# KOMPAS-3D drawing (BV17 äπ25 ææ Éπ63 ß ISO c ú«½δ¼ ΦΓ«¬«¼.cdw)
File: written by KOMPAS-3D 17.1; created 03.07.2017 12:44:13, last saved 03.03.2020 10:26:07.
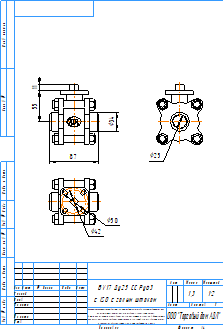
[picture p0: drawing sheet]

Sheet 1: A4, portrait

Title block, sheet 1: name: BV17 Ду25 СС Ру63 / с ISO c голым штоком; material: Сталь 20  ГОСТ 1050-88; mass: 1,3; sheets: 1; sheet format: A4; stored path: C:\Users\kka\KOMPAS_Work\!Trash\СС02 СС03 ФФ Смотровые стекла\СС01.cdw

Views: Спереди 4, Проекционный вид 5, Проекционный вид 6
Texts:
  Klimkovich
  ADL
  Рама для чертежей
  Лит-Масса-Масштаб
  Материал-Предприятие
  Масштаб
  Изм.
  Лист
  № докум.
  Подп.
  Дата
  Лит.
  Разраб.
  Пров.
  Т.контр.
  Листов
  Внимание! Данный продукт является объектом авторского права ООО «Торговый Дом АДЛ».
  Запрещается изменение, копирование, распространение
  (в том числе путем копирования на другие сайты и ресурсы в Интернете)
  или любое иное использование информации и объектов без предварительного
  согласия правообладателя (ООО «Торговый Дом АДЛ»).
  Н.контр.
  Утв.
  ООО "Торговый дом АДЛ"
  Изменение
  Номер документа
  Подпись
  Обозначение документа
  Наименование изделия
  Масса изделия по ГОСТ 2.109-73
  Порядковый номер листа
  Общее количество листов в документе
  Характер работы, выполненной лицом, подписавшим документ
  Наименование или индекс предприятия, выпускающего документ
  Инв. № подл.
  Подп. и дата
  Взам. инв. №
  Инв. № дубл.
  Инвентарный номер подлинника по ГОСТ 2.501-68
  Подпись принявшего подлинник в отдел технической документации
  Инвентарный номер подлинника, взамен которого выпущен данный подлинник
  Инвентарный номер дубликата по ГОСТ 2.502-68
  Подпись принявшего дубликат в отдел технической документации
  Справ. №
  Перв. примен.
  Обозначение документа, взамен или на основании которого выпущен данный документ
  Обозначение документа, в котором впервые записан данный документ
  Подпись лица, копировавшего чертеж
  Обозначение формата листа
  !Рама для чертежа
Dimensions and other numbers on the sheet: 87; 55; 34; 11; 50; 42; 25; 1:2; 1; 1,3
